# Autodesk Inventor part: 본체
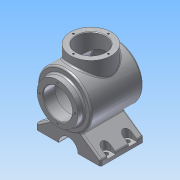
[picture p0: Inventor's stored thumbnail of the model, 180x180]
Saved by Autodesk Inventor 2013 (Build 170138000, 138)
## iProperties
Created: 2017-04
Part Number: 본체
Material: 알루미늄 6061
Document SubType Name: Modeling
Designer: MR
Density: 2.71 g/cm^3
Mass: 1670.99 g
Surface Area: 1067.84 cm^2
Volume: 616.6 cm^3
Author: MR
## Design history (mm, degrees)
sketch "스케치1"
  geometry: L1 (60, -40)-(-60, -40); L2 (-60, -40)-(-60, 40); L3 (-60, 40)-(60, 40); L4 (60, 40)-(60, -40); L5 (60, -40)-(-60, 40); 2 further points
  constraints: 10 end point, 2 parallel, 1 coincident, 1 horizontal, 1 midpoint, 1 perpendicular
  dimensions: "d0" = 120 distance of L2.end L3.end; "d1" = 80 distance of L1.end L2.end
extrude "돌출1" new body sketch "스케치1" distance "d2" = 10; taper "d3" = 0 deg
node "작업 평면1"
sketch "스케치2"
  geometry: L1 (0, 0)-(0, 82); C1 r 50 at (0, 82)
  constraints: 2 end point, 1 centre point, 1 coincident, 1 vertical
  dimensions: "d5" = 82 distance of L1.start L1.end; "d6" = 100 diameter of C1
extrude "돌출2" join sketch "스케치2" distance "d7" = 108; taper "d8" = 0 deg
sketch "스케치3"
  geometry: L1 (10, -40)-(0, -40) reference; L2 (0, -40)-(0, 40) reference; L3 (0, 40)-(10, 40) reference; L4 (10, 40)-(10, -40) reference; L5 (32, -60)-(32, 48) reference; L6 (32, 48)-(132, 48) reference; L7 (132, 48)-(132, -60) reference; L8 (132, -60)-(32, -60) reference; L9 (82, 53)-(82, -60); L10 (82, -60)-(132, -60); L11 (132, -60)-(132, -48.336); A1 r 113 centre (82, 53) between (82, -60) and (132, -48.336); 1 further point
  constraints: 6 end point, 2 collinear, 2 point on circle, 1 centre point, 1 midpoint, 1 perpendicular, 1 point on line, 1 tangent
  dimensions: "d10" = 113 radius of A1
revolve "회전1" sketch "스케치3" stored, may be unused: angle "d12" = 90 deg
sketch "스케치4"
  geometry: L1 (32, -48.336)-(32, 48) reference; L2 (32, 48)-(132, 48) reference; L3 (132, 48)-(132, -48.336) reference; L4 (10, -40)-(0, -40) reference; L5 (0, -40)-(0, 40) reference; L6 (0, 40)-(10, 40) reference; L7 (10, 40)-(10, -40) reference; L8 (82, 53)-(82, -60); L9 (122, 38)-(122, -41.916); L10 (82, 38)-(122, 38); L11 (82, 38)-(82, -50); A1 r 113 centre (82, 53) between (82, -60) and (132, -48.336) reference; A2 r 113 centre (82, 53) between (32, -48.336) and (82, -60) reference; A3 r 103 centre (82, 53) between (82, -50) and (122, -41.916); 1 further point
  constraints: 8 end point, 3 parallel, 2 point on circle, 1 centre point, 1 collinear, 1 point on line
  dimensions: "d13" = 10 radial gap between concentric circles of A2 A3; "d14" = 10 distance between parallel lines of L3 L9; "d15" = 10 distance between parallel lines of L10 L2
revolve "회전2" sketch "스케치4" stored, may be unused: angle "d16" = 90 deg
sketch "스케치5"
  geometry: C1 r 50 at (0, 0) reference; C2 r 38 at (0, 0); 1 further point
  constraints: 1 centre point, 1 coincident
  dimensions: "d21" = 76 diameter of C2
extrude "돌출3" join sketch "스케치5" distance "d22" = 12; taper "d23" = 0 deg
node "작업 평면2"
sketch "스케치7"
  geometry: L1 (120, 0)-(120, 10) reference; L2 (0, 10)-(120, 10) reference; L3 (0, 0)-(0, 10) reference; L4 (0, 10)-(38.416, 36.899); L5 (120, 10)-(81.584, 36.899); A1 r 50 centre (60, 82) between (38.416, 36.899) and (81.584, 36.899) reference; 1 further point
  constraints: 4 end point, 2 point on circle
  dimensions: "d28" = 55 deg angle of L1 L5; "d29" = 55 deg angle of L3 L4
extrude "돌출5" join sketch "스케치7" stored distance "d30" = 12; taper "d31" = 0 deg
sketch "스케치8"
  geometry: C1 r 18 at (60, 0); 1 further point
  constraints: 1 centre point, 1 coincident
  dimensions: "d32" = 36 diameter of C1
extrude "돌출6" cut sketch "스케치8" stored distance "d33" = 12; taper "d34" = 0 deg
sketch "스케치9"
  geometry: C1 r 38 at (0, 0) reference; C2 r 27 at (0, 0); 1 further point
  constraints: 1 centre point, 1 coincident
  dimensions: "d35" = 54 diameter of C2
extrude "돌출7" cut sketch "스케치9" distance "d36" = 22; taper "d37" = 0 deg
sketch "스케치11" dims "d41" = 65
  geometry: L1 (0, 0)-(0, 32.5); C1 r 38 at (0, 0) reference; 2 further points
  constraints: 2 coincident, 2 end point, 1 vertical, 1 vertical alignment, 2 other
hole "구멍1" sketch "스케치11" at (0, 32.5) diameter "d43" = 3.242; stored, may be unused: countersink angle "d47" = 90 deg, drill point angle "d49" = 118 deg; dims "d44" = 8, "d45" = 4, "d46" = 2, "d48" = 10
node "작업 평면3"
sketch "스케치13"
  geometry: L1 (-60, -40)-(-21.584, -40) reference; L2 (-60, 40)-(-60, -40) reference; L3 (-60, -20)-(-21.584, -20); L4 (-50, 40)-(-50, -40); L5 (-50, -28)-(-60, -28); L6 (-50, -12)-(-60, -12); A1 r 8 centre (-50, -20) between (-50, -28) and (-50, -12); 1 further point
  constraints: 8 end point, 6 point on line, 2 parallel, 2 perpendicular, 2 point on circle, 2 tangent, 1 centre point
  dimensions: "d65" = 20 distance between parallel lines of L3 L1; "d66" = 10 distance between parallel lines of L2 L4; "d67" = 16 diameter of A1
extrude "돌출9" cut sketch "스케치13" distance "d68" = 24; taper "d69" = 0 deg
sketch "스케치14"
  geometry: C1 r 4 at (50, 20); A1 r 8 centre (50, 20) between (50, 28) and (50, 12) reference; 1 further point
  constraints: 1 centre point, 1 coincident
  dimensions: "d70" = 8 diameter of C1
extrude "돌출10" cut sketch "스케치14" stored distance "d71" = 24; taper "d72" = 0 deg
fillet "모깎기1" dims "d73" = 3
fillet "모깎기2" dims "d74" = 3
fillet "모깎기3" dims "d75" = 3
fillet "모깎기4" dims "d76" = 3
chamfer "모따기1" distance "d77" = 1; stored, may be unused: second distance "d78" = 2, angle "d79" = 45 deg
node "작업 평면4"
sketch "스케치15"
  geometry: C1 r 50 at (0, 0) reference; 2 further points
  constraints: 1 coincident, 1 other
feature "엠보싱1" sketch "스케치15" dims "d10" = 113, "d80" = 0.5, "d81" = 0
node "작업 평면5"
sketch "스케치16"
  geometry: L1 (-47, 48)-(47, 48) reference; L2 (0, 48)-(0, -2); C1 r 38 at (0, -2); 1 further point
  constraints: 2 end point, 1 centre point, 1 coincident, 1 midpoint, 1 perpendicular
  dimensions: "d84" = 50 distance of L2.start L2.end; "d85" = 76 diameter of C1
extrude "돌출11" join sketch "스케치16" stored distance "d86" = 10; taper "d87" = 0 deg
sketch "스케치17"
  geometry: C1 r 38 at (0, 0) reference; C2 r 27 at (0, 0); 1 further point
  constraints: 1 centre point, 1 coincident
  dimensions: "d88" = 54 diameter of C2
extrude "돌출12" cut sketch "스케치17" distance "d89" = 40; taper "d90" = 0 deg
sketch "스케치18" dims "d91" = 65
  geometry: L1 (0, 0)-(-32.5, 0); C1 r 38 at (0, 0) reference; 2 further points
  constraints: 2 coincident, 2 end point, 1 horizontal, 1 horizontal alignment, 2 other
hole "구멍3" sketch "스케치18" at (-32.5, 0) diameter "d92" = 3.242; stored, may be unused: countersink angle "d96" = 90 deg, drill point angle "d98" = 118 deg; dims "d93" = 8, "d94" = 4, "d95" = 2, "d97" = 10
fillet "모깎기5" dims "d102" = 3
chamfer "모따기2" distance "d103" = 1; stored, may be unused: second distance "d104" = 2, angle "d105" = 45 deg
node "솔리드1"
pattern_circular "원형 패턴1" dims angle "d51" = 360 deg
mirror "대칭1"
mirror "대칭2"
pattern_circular "원형 패턴3" dims angle "d100" = 360 deg
node "절단 모서리 투영1"
node "절단 모서리 투영2"
other parameters: "d4" = 48, "d9" = 226, "d17" = 0.5, "d18" = 2, "d19" = 0, "d24" = 147, "d83" = 147
